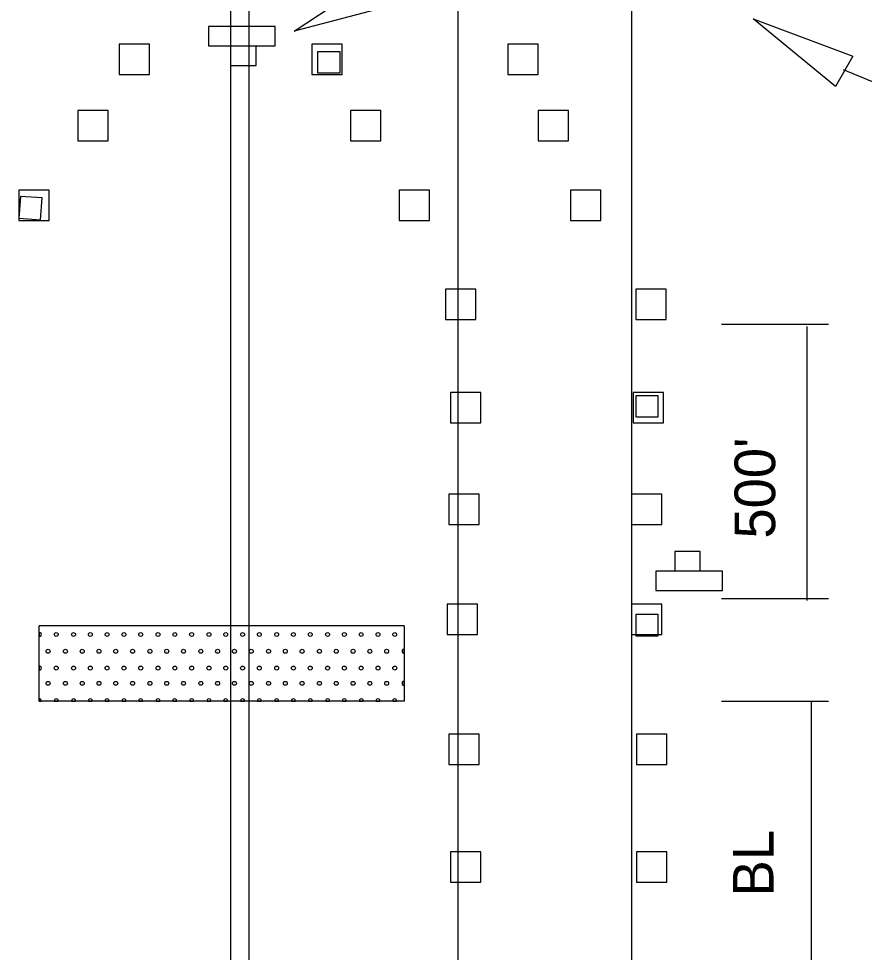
# Model space of a CAD drawing. Extents: x 1531.38 to 1538.58, y 1529.59 to 1539.28.
# Drawn here: x 1535.591 to 1536.84, y 1535.077 to 1536.457 of the extents above; entities that cross this region are included whole.
import ezdxf

# ---------------------------------------------------------------- set-up
doc = ezdxf.new("R2010")
doc.units = 0
for name, color, linetype in [('DETL-DIMS', 7, 'Continuous'), ('DETL-LINE', 7, 'Continuous'), ('DETL-NOTE', 7, 'Continuous'), ('USER-BORD', 7, 'Continuous')]:
    doc.layers.add(name, color=color, linetype=linetype)

# ---------------------------------------------------------------- blocks, each defined once
blk = doc.blocks.new('CD20')
at = {"layer": 'USER-BORD'}
blk.add_lwpolyline([(-0.0625, -0.0625), (0, -0.0625), (0, 0), (-0.0625, 0)], close=True, dxfattribs=at)
blk = doc.blocks.new('SIGN13')
at = {"layer": 'USER-BORD'}
for points in [[(-0.0134, 0.0182), (0.011, 0.0189), (0.011, 0.0371), (-0.0134, 0.0371)], [(-0.0314, 0.0182), (-0.0314, 0), (0.032, 0), (0.032, 0.0182)]]:
    blk.add_lwpolyline(points, close=True, dxfattribs=at)

msp = doc.modelspace()

# ---------------------------------------------------------------- linework, layer by layer
at = {"layer": 'DETL-DIMS'}
for p, q in [((1536.8087, 1536.3815), (1537.1301, 1536.2471)), ((1536.6291, 1536.0055), (1536.7871, 1536.0055)), ((1536.7551, 1536.0019), (1536.7551, 1535.5969)), ((1536.6291, 1535.6003), (1536.7871, 1535.6003)), ((1536.6291, 1535.4484), (1536.7871, 1535.4484)), ((1536.7613, 1535.4484), (1536.7613, 1533.1366))]:
    msp.add_line(p, q, dxfattribs=at)
for points in [[(1536.1288, 1536.525), (1536.1499, 1536.478), (1535.9979, 1536.4382)], [(1536.8231, 1536.4011), (1536.7972, 1536.3563), (1536.6759, 1536.4563)]]:
    msp.add_lwpolyline(points, close=True, dxfattribs=at)
at = {"layer": 'DETL-LINE'}
for p, q in [((1536.2393, 1538.948), (1536.2393, 1535.6775)), ((1535.9039, 1538.9346), (1535.9039, 1531.7918)), ((1535.9309, 1538.9346), (1535.9309, 1531.7918)), ((1536.4962, 1538.9346), (1536.4962, 1531.7918)), ((1536.2393, 1535.6775), (1536.2393, 1531.8053)), ((1535.6214, 1535.4485), (1535.6214, 1535.5595)), ((1536.1603, 1535.5595), (1535.6214, 1535.5595)), ((1535.6214, 1535.4485), (1535.6214, 1535.5595)), ((1536.1603, 1535.5595), (1535.6214, 1535.5595)), ((1535.6216, 1535.547), (1535.6216, 1535.547)), ((1535.6464, 1535.547), (1535.6464, 1535.547)), ((1535.672, 1535.547), (1535.672, 1535.547)), ((1535.6968, 1535.547), (1535.6968, 1535.547)), ((1535.7216, 1535.547), (1535.7216, 1535.547)), ((1535.7464, 1535.547), (1535.7464, 1535.547)), ((1535.7712, 1535.547), (1535.7712, 1535.547)), ((1535.7968, 1535.547), (1535.7968, 1535.547)), ((1535.8216, 1535.547), (1535.8216, 1535.547)), ((1535.8464, 1535.547), (1535.8464, 1535.547)), ((1535.872, 1535.547), (1535.872, 1535.547)), ((1535.8968, 1535.547), (1535.8968, 1535.547)), ((1535.9216, 1535.547), (1535.9216, 1535.547)), ((1535.9464, 1535.547), (1535.9464, 1535.547)), ((1535.972, 1535.547), (1535.972, 1535.547)), ((1535.9968, 1535.547), (1535.9968, 1535.547)), ((1536.0216, 1535.547), (1536.0216, 1535.547)), ((1536.0472, 1535.547), (1536.0472, 1535.547)), ((1536.072, 1535.547), (1536.072, 1535.547)), ((1536.0968, 1535.547), (1536.0968, 1535.547)), ((1536.1216, 1535.547), (1536.1216, 1535.547)), ((1536.1464, 1535.547), (1536.1464, 1535.547)), ((1536.1603, 1535.5595), (1536.1603, 1535.4485)), ((1536.1603, 1535.5595), (1536.1603, 1535.4485)), ((1535.6344, 1535.5222), (1535.6344, 1535.5222)), ((1535.6344, 1535.5222), (1535.6344, 1535.5222)), ((1535.6592, 1535.5222), (1535.6592, 1535.5222)), ((1535.66, 1535.5222), (1535.66, 1535.5222)), ((1535.684, 1535.5222), (1535.684, 1535.5222)), ((1535.6848, 1535.5222), (1535.6848, 1535.5222)), ((1535.7088, 1535.5222), (1535.7088, 1535.5222)), ((1535.7096, 1535.5222), (1535.7096, 1535.5222)), ((1535.7344, 1535.5222), (1535.7344, 1535.5222)), ((1535.7344, 1535.5222), (1535.7344, 1535.5222)), ((1535.7592, 1535.5222), (1535.7592, 1535.5222)), ((1535.7592, 1535.5222), (1535.7592, 1535.5222)), ((1535.784, 1535.5222), (1535.784, 1535.5222)), ((1535.7848, 1535.5222), (1535.7848, 1535.5222)), ((1535.8088, 1535.5222), (1535.8088, 1535.5222)), ((1535.8096, 1535.5222), (1535.8096, 1535.5222)), ((1535.8344, 1535.5222), (1535.8344, 1535.5222)), ((1535.8344, 1535.5222), (1535.8344, 1535.5222)), ((1535.8592, 1535.5222), (1535.8592, 1535.5222)), ((1535.86, 1535.5222), (1535.86, 1535.5222)), ((1535.884, 1535.5222), (1535.884, 1535.5222)), ((1535.8848, 1535.5222), (1535.8848, 1535.5222)), ((1535.9088, 1535.5222), (1535.9088, 1535.5222)), ((1535.9096, 1535.5222), (1535.9096, 1535.5222)), ((1535.9344, 1535.5222), (1535.9344, 1535.5222)), ((1535.9344, 1535.5222), (1535.9344, 1535.5222)), ((1535.9592, 1535.5222), (1535.9592, 1535.5222)), ((1535.96, 1535.5222), (1535.96, 1535.5222)), ((1535.984, 1535.5222), (1535.984, 1535.5222)), ((1535.9848, 1535.5222), (1535.9848, 1535.5222)), ((1536.0096, 1535.5222), (1536.0096, 1535.5222)), ((1536.0096, 1535.5222), (1536.0096, 1535.5222)), ((1536.0344, 1535.5222), (1536.0344, 1535.5222)), ((1536.0352, 1535.5222), (1536.0352, 1535.5222)), ((1536.0592, 1535.5222), (1536.0592, 1535.5222)), ((1536.06, 1535.5222), (1536.06, 1535.5222)), ((1536.084, 1535.5222), (1536.084, 1535.5222)), ((1536.0848, 1535.5222), (1536.0848, 1535.5222)), ((1536.1096, 1535.5222), (1536.1096, 1535.5222)), ((1536.1096, 1535.5222), (1536.1096, 1535.5222)), ((1536.1344, 1535.5222), (1536.1344, 1535.5222)), ((1536.1344, 1535.5222), (1536.1344, 1535.5222)), ((1536.1592, 1535.5222), (1536.1592, 1535.5222)), ((1536.16, 1535.5222), (1536.16, 1535.5222)), ((1535.6216, 1535.4974), (1535.6216, 1535.4974)), ((1535.6216, 1535.4974), (1535.6216, 1535.4974)), ((1535.6464, 1535.4974), (1535.6464, 1535.4974)), ((1535.6464, 1535.4974), (1535.6464, 1535.4974)), ((1535.672, 1535.4974), (1535.672, 1535.4974)), ((1535.672, 1535.4974), (1535.672, 1535.4974)), ((1535.6968, 1535.4974), (1535.6968, 1535.4974)), ((1535.6968, 1535.4974), (1535.6968, 1535.4974)), ((1535.7216, 1535.4974), (1535.7216, 1535.4974)), ((1535.7216, 1535.4974), (1535.7216, 1535.4974)), ((1535.7464, 1535.4974), (1535.7464, 1535.4974)), ((1535.7464, 1535.4974), (1535.7464, 1535.4974)), ((1535.7712, 1535.4974), (1535.7712, 1535.4974)), ((1535.7712, 1535.4974), (1535.7712, 1535.4974)), ((1535.7968, 1535.4974), (1535.7968, 1535.4974)), ((1535.7968, 1535.4974), (1535.7968, 1535.4974)), ((1535.8216, 1535.4974), (1535.8216, 1535.4974)), ((1535.8216, 1535.4974), (1535.8216, 1535.4974)), ((1535.8464, 1535.4974), (1535.8464, 1535.4974)), ((1535.8464, 1535.4974), (1535.8464, 1535.4974)), ((1535.872, 1535.4974), (1535.872, 1535.4974)), ((1535.872, 1535.4974), (1535.872, 1535.4974)), ((1535.8968, 1535.4974), (1535.8968, 1535.4974)), ((1535.8968, 1535.4974), (1535.8968, 1535.4974)), ((1535.9216, 1535.4974), (1535.9216, 1535.4974)), ((1535.9216, 1535.4974), (1535.9216, 1535.4974)), ((1535.9464, 1535.4974), (1535.9464, 1535.4974)), ((1535.9464, 1535.4974), (1535.9464, 1535.4974)), ((1535.972, 1535.4974), (1535.972, 1535.4974)), ((1535.972, 1535.4974), (1535.972, 1535.4974)), ((1535.9968, 1535.4974), (1535.9968, 1535.4974)), ((1535.9968, 1535.4974), (1535.9968, 1535.4974)), ((1536.0216, 1535.4974), (1536.0216, 1535.4974)), ((1536.0216, 1535.4974), (1536.0216, 1535.4974)), ((1536.0472, 1535.4974), (1536.0472, 1535.4974)), ((1536.0472, 1535.4974), (1536.0472, 1535.4974)), ((1536.072, 1535.4974), (1536.072, 1535.4974)), ((1536.072, 1535.4974), (1536.072, 1535.4974)), ((1536.0968, 1535.4974), (1536.0968, 1535.4974)), ((1536.0968, 1535.4974), (1536.0968, 1535.4974)), ((1536.1216, 1535.4974), (1536.1216, 1535.4974)), ((1536.1216, 1535.4974), (1536.1216, 1535.4974)), ((1536.1464, 1535.4974), (1536.1464, 1535.4974)), ((1536.1464, 1535.4974), (1536.1464, 1535.4974)), ((1535.6344, 1535.4748), (1535.6344, 1535.4748)), ((1535.6344, 1535.4748), (1535.6344, 1535.4748)), ((1535.6592, 1535.4748), (1535.6592, 1535.4748)), ((1535.66, 1535.4748), (1535.66, 1535.4748)), ((1535.684, 1535.4748), (1535.684, 1535.4748)), ((1535.6848, 1535.4748), (1535.6848, 1535.4748)), ((1535.7088, 1535.4748), (1535.7088, 1535.4748)), ((1535.7096, 1535.4748), (1535.7096, 1535.4748)), ((1535.7344, 1535.4748), (1535.7344, 1535.4748)), ((1535.7344, 1535.4748), (1535.7344, 1535.4748)), ((1535.7592, 1535.4748), (1535.7592, 1535.4748)), ((1535.7592, 1535.4748), (1535.7592, 1535.4748)), ((1535.784, 1535.4748), (1535.784, 1535.4748)), ((1535.7848, 1535.4748), (1535.7848, 1535.4748)), ((1535.8088, 1535.4748), (1535.8088, 1535.4748)), ((1535.8096, 1535.4748), (1535.8096, 1535.4748)), ((1535.8344, 1535.4748), (1535.8344, 1535.4748)), ((1535.8344, 1535.4748), (1535.8344, 1535.4748)), ((1535.8592, 1535.4748), (1535.8592, 1535.4748)), ((1535.86, 1535.4748), (1535.86, 1535.4748)), ((1535.884, 1535.4748), (1535.884, 1535.4748)), ((1535.8848, 1535.4748), (1535.8848, 1535.4748)), ((1535.9088, 1535.4748), (1535.9088, 1535.4748)), ((1535.9096, 1535.4748), (1535.9096, 1535.4748)), ((1535.9344, 1535.4748), (1535.9344, 1535.4748)), ((1535.9344, 1535.4748), (1535.9344, 1535.4748)), ((1535.9592, 1535.4748), (1535.9592, 1535.4748)), ((1535.96, 1535.4748), (1535.96, 1535.4748)), ((1535.984, 1535.4748), (1535.984, 1535.4748)), ((1535.9848, 1535.4748), (1535.9848, 1535.4748)), ((1536.0096, 1535.4748), (1536.0096, 1535.4748)), ((1536.0096, 1535.4748), (1536.0096, 1535.4748)), ((1536.0344, 1535.4748), (1536.0344, 1535.4748)), ((1536.0352, 1535.4748), (1536.0352, 1535.4748)), ((1536.0592, 1535.4748), (1536.0592, 1535.4748)), ((1536.06, 1535.4748), (1536.06, 1535.4748)), ((1536.084, 1535.4748), (1536.084, 1535.4748)), ((1536.0848, 1535.4748), (1536.0848, 1535.4748)), ((1536.1096, 1535.4748), (1536.1096, 1535.4748)), ((1536.1096, 1535.4748), (1536.1096, 1535.4748)), ((1536.1344, 1535.4748), (1536.1344, 1535.4748)), ((1536.1344, 1535.4748), (1536.1344, 1535.4748)), ((1536.1592, 1535.4748), (1536.1592, 1535.4748)), ((1536.16, 1535.4748), (1536.16, 1535.4748)), ((1536.1603, 1535.4485), (1535.6214, 1535.4485)), ((1536.1603, 1535.4485), (1535.6214, 1535.4485)), ((1535.6216, 1535.4492), (1535.6216, 1535.4492)), ((1535.6464, 1535.4492), (1535.6464, 1535.4492)), ((1535.672, 1535.4492), (1535.672, 1535.4492)), ((1535.6968, 1535.4492), (1535.6968, 1535.4492)), ((1535.7216, 1535.4492), (1535.7216, 1535.4492)), ((1535.7464, 1535.4492), (1535.7464, 1535.4492)), ((1535.7712, 1535.4492), (1535.7712, 1535.4492)), ((1535.7968, 1535.4492), (1535.7968, 1535.4492)), ((1535.8216, 1535.4492), (1535.8216, 1535.4492)), ((1535.8464, 1535.4492), (1535.8464, 1535.4492)), ((1535.872, 1535.4492), (1535.872, 1535.4492)), ((1535.8968, 1535.4492), (1535.8968, 1535.4492)), ((1535.9216, 1535.4492), (1535.9216, 1535.4492)), ((1535.9464, 1535.4492), (1535.9464, 1535.4492)), ((1535.972, 1535.4492), (1535.972, 1535.4492)), ((1535.9968, 1535.4492), (1535.9968, 1535.4492)), ((1536.0216, 1535.4492), (1536.0216, 1535.4492)), ((1536.0472, 1535.4492), (1536.0472, 1535.4492)), ((1536.072, 1535.4492), (1536.072, 1535.4492)), ((1536.0968, 1535.4492), (1536.0968, 1535.4492)), ((1536.1216, 1535.4492), (1536.1216, 1535.4492)), ((1536.1464, 1535.4492), (1536.1464, 1535.4492))]:
    msp.add_line(p, q, dxfattribs=at)
for points in [[(1535.7393, 1536.3742), (1535.7841, 1536.3742), (1535.7841, 1536.419), (1535.7393, 1536.419)], [(1536.0237, 1536.3742), (1536.0685, 1536.3742), (1536.0685, 1536.419), (1536.0237, 1536.419)], [(1536.3136, 1536.3742), (1536.3584, 1536.3742), (1536.3584, 1536.419), (1536.3136, 1536.419)], [(1535.6783, 1536.2761), (1535.7231, 1536.2761), (1535.7231, 1536.3209), (1535.6783, 1536.3209)], [(1536.0808, 1536.2761), (1536.1256, 1536.2761), (1536.1256, 1536.3209), (1536.0808, 1536.3209)], [(1536.3581, 1536.2761), (1536.4029, 1536.2761), (1536.4029, 1536.3209), (1536.3581, 1536.3209)], [(1535.591, 1536.1583), (1535.6358, 1536.1583), (1535.6358, 1536.2031), (1535.591, 1536.2031)], [(1536.1527, 1536.1583), (1536.1975, 1536.1583), (1536.1975, 1536.2031), (1536.1527, 1536.2031)], [(1536.406, 1536.1583), (1536.4508, 1536.1583), (1536.4508, 1536.2031), (1536.406, 1536.2031)], [(1536.2212, 1536.0121), (1536.266, 1536.0121), (1536.266, 1536.0569), (1536.2212, 1536.0569)], [(1536.5025, 1536.0121), (1536.5473, 1536.0121), (1536.5473, 1536.0569), (1536.5025, 1536.0569)], [(1536.2286, 1535.8595), (1536.2734, 1535.8595), (1536.2734, 1535.9043), (1536.2286, 1535.9043)], [(1536.4986, 1535.8595), (1536.5434, 1535.8595), (1536.5434, 1535.9043), (1536.4986, 1535.9043)], [(1536.2263, 1535.7092), (1536.2711, 1535.7092), (1536.2711, 1535.754), (1536.2263, 1535.754)], [(1536.4962, 1535.7092), (1536.541, 1535.7092), (1536.541, 1535.754), (1536.4962, 1535.754)], [(1536.2239, 1535.5471), (1536.2687, 1535.5471), (1536.2687, 1535.5919), (1536.2239, 1535.5919)], [(1536.4962, 1535.5471), (1536.541, 1535.5471), (1536.541, 1535.5919), (1536.4962, 1535.5919)], [(1536.2263, 1535.3546), (1536.2711, 1535.3546), (1536.2711, 1535.3994), (1536.2263, 1535.3994)], [(1536.5033, 1535.3546), (1536.5481, 1535.3546), (1536.5481, 1535.3994), (1536.5033, 1535.3994)], [(1536.2286, 1535.1808), (1536.2734, 1535.1808), (1536.2734, 1535.2256), (1536.2286, 1535.2256)], [(1536.5033, 1535.1808), (1536.5481, 1535.1808), (1536.5481, 1535.2256), (1536.5033, 1535.2256)]]:
    msp.add_lwpolyline(points, close=True, dxfattribs=at)
for points in [[(1535.6214, 1535.5498), (1535.6214, 1535.544)], [(1536.1603, 1535.5192), (1536.1603, 1535.525)], [(1535.6214, 1535.5002), (1535.6214, 1535.4944)], [(1536.1603, 1535.4718), (1536.1603, 1535.4776)], [(1535.6214, 1535.452), (1535.6214, 1535.4485), (1535.6244, 1535.4485)], [(1535.6436, 1535.4485), (1535.6492, 1535.4485)], [(1535.6692, 1535.4485), (1535.6748, 1535.4485)], [(1535.694, 1535.4485), (1535.6996, 1535.4485)], [(1535.7188, 1535.4485), (1535.7244, 1535.4485)], [(1535.7436, 1535.4485), (1535.7492, 1535.4485)], [(1535.7684, 1535.4485), (1535.774, 1535.4485)], [(1535.794, 1535.4485), (1535.7996, 1535.4485)], [(1535.8188, 1535.4485), (1535.8244, 1535.4485)], [(1535.8436, 1535.4485), (1535.8492, 1535.4485)], [(1535.8692, 1535.4485), (1535.8748, 1535.4485)], [(1535.894, 1535.4485), (1535.8996, 1535.4485)], [(1535.9188, 1535.4485), (1535.9244, 1535.4485)], [(1535.9436, 1535.4485), (1535.9492, 1535.4485)], [(1535.9692, 1535.4485), (1535.9748, 1535.4485)], [(1535.994, 1535.4485), (1535.9996, 1535.4485)], [(1536.0188, 1535.4485), (1536.0244, 1535.4485)], [(1536.0444, 1535.4485), (1536.05, 1535.4485)], [(1536.0692, 1535.4485), (1536.0748, 1535.4485)], [(1536.094, 1535.4485), (1536.0996, 1535.4485)], [(1536.1188, 1535.4485), (1536.1244, 1535.4485)], [(1536.1436, 1535.4485), (1536.1492, 1535.4485)]]:
    msp.add_lwpolyline(points, dxfattribs=at)
for centre in [(1535.6464, 1535.5469), (1535.672, 1535.5469), (1535.6968, 1535.5469), (1535.7216, 1535.5469), (1535.7464, 1535.5469), (1535.7712, 1535.5469), (1535.7968, 1535.5469), (1535.8216, 1535.5469), (1535.8464, 1535.5469), (1535.872, 1535.5469), (1535.8968, 1535.5469), (1535.9216, 1535.5469), (1535.9464, 1535.5469), (1535.972, 1535.5469), (1535.9968, 1535.5469), (1536.0216, 1535.5469), (1536.0472, 1535.5469), (1536.072, 1535.5469), (1536.0968, 1535.5469), (1536.1216, 1535.5469), (1536.1464, 1535.5469), (1535.6344, 1535.5221), (1535.66, 1535.5221), (1535.6848, 1535.5221), (1535.7096, 1535.5221), (1535.7344, 1535.5221), (1535.7592, 1535.5221), (1535.7848, 1535.5221), (1535.8096, 1535.5221), (1535.8344, 1535.5221), (1535.86, 1535.5221), (1535.8848, 1535.5221), (1535.9096, 1535.5221), (1535.9344, 1535.5221), (1535.96, 1535.5221), (1535.9848, 1535.5221), (1536.0096, 1535.5221), (1536.0352, 1535.5221), (1536.06, 1535.5221), (1536.0848, 1535.5221), (1536.1096, 1535.5221), (1536.1344, 1535.5221), (1535.6464, 1535.4973), (1535.672, 1535.4973), (1535.6968, 1535.4973), (1535.7216, 1535.4973), (1535.7464, 1535.4973), (1535.7712, 1535.4973), (1535.7968, 1535.4973), (1535.8216, 1535.4973), (1535.8464, 1535.4973), (1535.872, 1535.4973), (1535.8968, 1535.4973), (1535.9216, 1535.4973), (1535.9464, 1535.4973), (1535.972, 1535.4973), (1535.9968, 1535.4973), (1536.0216, 1535.4973), (1536.0472, 1535.4973), (1536.072, 1535.4973), (1536.0968, 1535.4973), (1536.1216, 1535.4973), (1536.1464, 1535.4973), (1535.6344, 1535.4747), (1535.66, 1535.4747), (1535.6848, 1535.4747), (1535.7096, 1535.4747), (1535.7344, 1535.4747), (1535.7592, 1535.4747), (1535.7848, 1535.4747), (1535.8096, 1535.4747), (1535.8344, 1535.4747), (1535.86, 1535.4747), (1535.8848, 1535.4747), (1535.9096, 1535.4747), (1535.9344, 1535.4747), (1535.96, 1535.4747), (1535.9848, 1535.4747), (1536.0096, 1535.4747), (1536.0352, 1535.4747), (1536.06, 1535.4747), (1536.0848, 1535.4747), (1536.1096, 1535.4747), (1536.1344, 1535.4747)]:
    msp.add_circle(centre, 0.00291, dxfattribs=at)
for centre, start, end in [((1535.6216, 1535.5469), 265.8762, 94.1238), ((1536.16, 1535.5221), 84.268, 275.732), ((1535.6216, 1535.4973), 265.8762, 94.1238), ((1536.16, 1535.4747), 84.268, 275.732), ((1535.6216, 1535.4491), 347.0446, 94.1238), ((1535.6464, 1535.4491), 347.0446, 192.9554), ((1535.672, 1535.4491), 347.0446, 192.9554), ((1535.6968, 1535.4491), 347.0446, 192.9554), ((1535.7216, 1535.4491), 347.0446, 192.9554), ((1535.7464, 1535.4491), 347.0446, 192.9554), ((1535.7712, 1535.4491), 347.0446, 192.9554), ((1535.7968, 1535.4491), 347.0446, 192.9554), ((1535.8216, 1535.4491), 347.0446, 192.9554), ((1535.8464, 1535.4491), 347.0446, 192.9554), ((1535.872, 1535.4491), 347.0446, 192.9554), ((1535.8968, 1535.4491), 347.0446, 192.9554), ((1535.9216, 1535.4491), 347.0446, 192.9554), ((1535.9464, 1535.4491), 347.0446, 192.9554), ((1535.972, 1535.4491), 347.0446, 192.9554), ((1535.9968, 1535.4491), 347.0446, 192.9554), ((1536.0216, 1535.4491), 347.0446, 192.9554), ((1536.0472, 1535.4491), 347.0446, 192.9554), ((1536.072, 1535.4491), 347.0446, 192.9554), ((1536.0968, 1535.4491), 347.0446, 192.9554), ((1536.1216, 1535.4491), 347.0446, 192.9554), ((1536.1464, 1535.4491), 347.0446, 192.9554)]:
    msp.add_arc(centre, 0.00291, start, end, dxfattribs=at)

# ---------------------------------------------------------------- block references
for name, p, xscale, yscale, rotation in [('SIGN13', (1535.9209, 1536.4449), 1.550372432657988, 1.550372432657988, 180), ('CD20', (1536.033, 1536.4083), 0.5153677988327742, -0.5153677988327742, 180), ('CD20', (1535.6256, 1536.1918), 0.5153677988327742, 0.5153677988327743, -4.162268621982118), ('CD20', (1536.5027, 1535.9002), 0.5153677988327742, -0.5153677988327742, 180), ('CD20', (1536.5027, 1535.5768), 0.5153677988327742, -0.5153677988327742, 180), ('CD20', (1536.5027, 1535.5768), 0.5153677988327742, -0.5153677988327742, 180), ('CD20', (1536.5027, 1535.5768), 0.5153677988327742, -0.5153677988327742, 180), ('CD20', (1536.5027, 1535.5768), 0.5153677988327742, -0.5153677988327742, 180), ('CD20', (1536.5027, 1535.5768), 0.5153677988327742, -0.5153677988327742, 180), ('CD20', (1536.5027, 1535.5768), 0.5153677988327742, -0.5153677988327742, 180), ('CD20', (1536.5027, 1535.5768), 0.5153677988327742, -0.5153677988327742, 180), ('CD20', (1536.5027, 1535.5768), 0.5153677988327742, -0.5153677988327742, 180), ('CD20', (1536.5027, 1535.5768), 0.5153677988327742, -0.5153677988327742, 180), ('CD20', (1536.5027, 1535.5768), 0.5153677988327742, -0.5153677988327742, 180), ('CD20', (1536.5027, 1535.5768), 0.5153677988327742, -0.5153677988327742, 180), ('CD20', (1536.5027, 1535.5768), 0.5153677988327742, -0.5153677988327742, 180), ('CD20', (1536.5027, 1535.5768), 0.5153677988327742, -0.5153677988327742, 180), ('CD20', (1536.5027, 1535.5768), 0.5153677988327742, -0.5153677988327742, 180), ('CD20', (1536.5027, 1535.5768), 0.5153677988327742, -0.5153677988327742, 180), ('CD20', (1536.5027, 1535.5768), 0.5153677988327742, -0.5153677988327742, 180), ('CD20', (1536.5027, 1535.5768), 0.5153677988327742, -0.5153677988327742, 180)]:
    msp.add_blockref(name, p, dxfattribs=dict(at, xscale=xscale, yscale=yscale, rotation=rotation))
at = {"layer": 'DETL-LINE', "xscale": 1.550372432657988, "yscale": 1.550372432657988}
msp.add_blockref('SIGN13', (1536.5806, 1535.612), dxfattribs=at)

# ---------------------------------------------------------------- texts
at = {"layer": 'DETL-NOTE'}
for s, p in [("500'", (1536.7082, 1535.6886)), ('BL', (1536.7058, 1535.1599))]:
    msp.add_text(s, height=0.06, rotation=90, dxfattribs=at).set_placement(p)

doc.saveas('drawing.dxf')
